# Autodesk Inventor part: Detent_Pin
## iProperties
Author: Ole Germer
Shininess: 60.0
PropertySet Name: _Private Model Information
Created: 2001-04
Part Number: Detent_Pin
Material: Steel, High Strength Low Alloy
Document SubType Name: Modeling
Designer: Ole Germer
Control State: 0
Master: False
Checked Out: False
PropertySet Name: Design Tracking Control
Density: 7.840000000000001
Volumn: 1.4912090777138438
Area: 11.91724761329502
PropertySet Name: Model Information
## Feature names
1. Extrusion1
2. Chamfer4
3. Extrusion3
4. Revolution2
5. Sweep1
6. Revolution1
